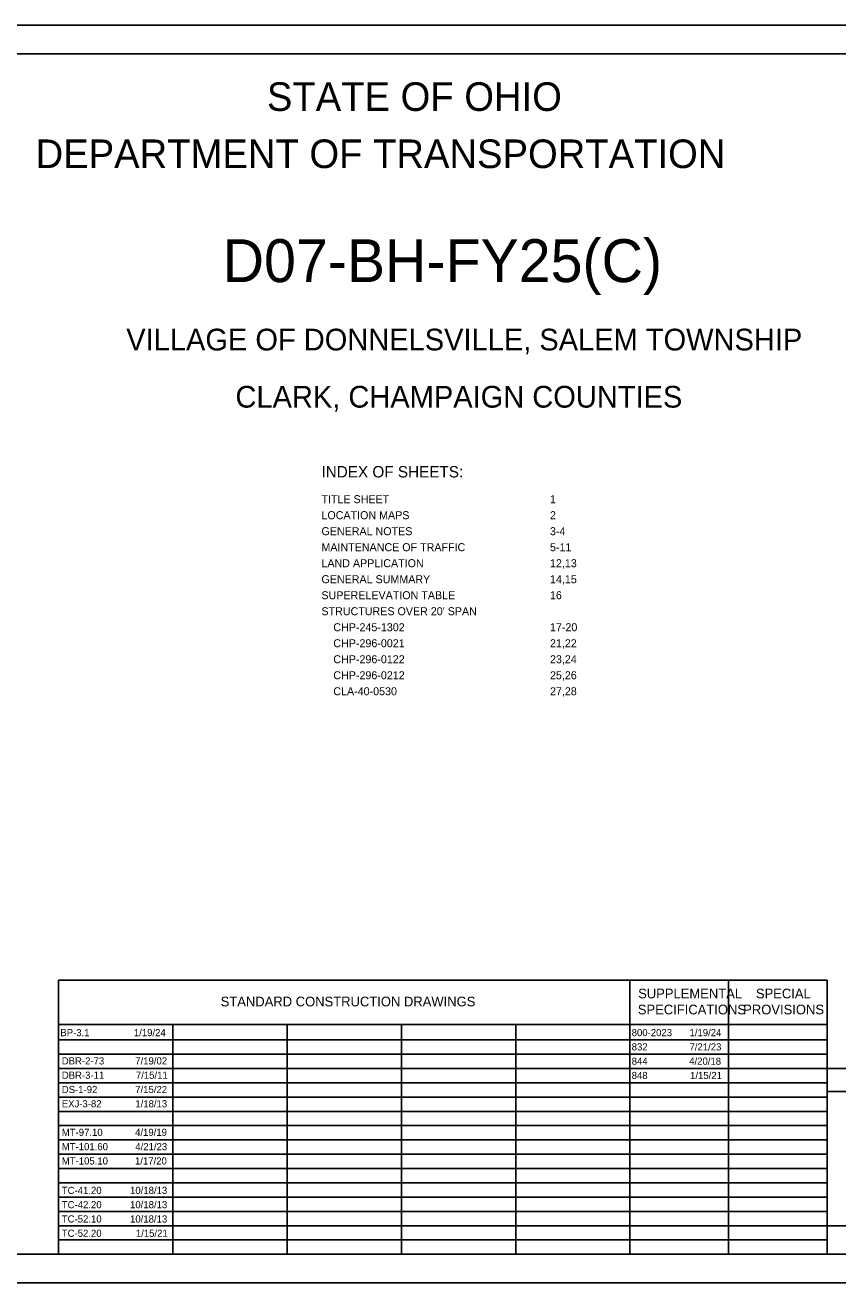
# Model space of a CAD drawing. Extents: x 0 to 36, y 0 to 22.
# Drawn here: x 9.56 to 23.79, y 0 to 22 of the extents above; entities that cross this region are included whole.
import ezdxf

# ---------------------------------------------------------------- set-up
doc = ezdxf.new("R2010")
doc.units = 0
for name, color, linetype in [('SH_Border', 7, 'Continuous'), ('SH_Cut_Line', 7, 'Continuous'), ('SH_Data', 7, 'Continuous'), ('SH_Text', 7, 'Continuous')]:
    doc.layers.add(name, color=color, linetype=linetype)

msp = doc.modelspace()

# ---------------------------------------------------------------- linework, layer by layer
at = {"layer": 'SH_Border'}
msp.add_lwpolyline([(1.5, 21.5), (33.5, 21.5), (33.5, 0.5), (1.5, 0.5)], close=True, dxfattribs=at)
at = {"layer": 'SH_Cut_Line'}
msp.add_lwpolyline([(0, 0), (34, 0), (34, 22), (0, 22)], close=True, dxfattribs=at)
at = {"layer": 'SH_Data'}
for p, q in [((10.15, 5.292), (23.6, 5.292)), ((10.15, 0.5), (10.15, 5.292)), ((20.15, 0.5), (20.15, 5.292)), ((21.875, 0.5), (21.875, 5.292)), ((23.6, 0.5), (23.6, 5.292)), ((10.15, 4.521), (23.6, 4.521)), ((12.15, 0.5), (12.15, 4.521)), ((14.15, 0.5), (14.15, 4.521)), ((16.15, 0.5), (16.15, 4.521)), ((18.15, 0.5), (18.15, 4.521)), ((10.15, 4.25), (23.6, 4.25)), ((10.15, 4), (23.6, 4)), ((10.15, 3.75), (23.6, 3.75)), ((23.6, 0.5), (23.6, 3.75)), ((23.6, 3.75), (26.4, 3.75)), ((10.15, 3.5), (23.6, 3.5)), ((23.6, 3.35), (26.4, 3.35)), ((10.15, 3.25), (23.6, 3.25)), ((10.15, 3), (23.6, 3)), ((10.15, 2.75), (23.6, 2.75)), ((10.15, 2.5), (23.6, 2.5)), ((10.15, 2.25), (23.6, 2.25)), ((10.15, 2), (23.6, 2)), ((10.15, 1.75), (23.6, 1.75)), ((10.15, 1.5), (23.6, 1.5)), ((10.15, 1.25), (23.6, 1.25)), ((10.15, 1), (23.6, 1)), ((10.15, 0.75), (23.6, 0.75)), ((23.6, 0.5), (26.4, 0.5))]:
    msp.add_line(p, q, dxfattribs=at)
msp.add_lwpolyline([(23.6, 0.5), (23.6, 1), (26.4, 1), (26.4, 0.5)], close=True, dxfattribs=at)

# ---------------------------------------------------------------- texts
at = {"layer": 'SH_Text'}
for s, height, p in [('STATE OF OHIO', 0.5, (13.795, 20.5)), ('DEPARTMENT OF TRANSPORTATION', 0.5, (9.747, 19.5)), ('D07-BH-FY25(C)', 0.75, (13.021, 17.505)), ('VILLAGE OF DONNELSVILLE, SALEM TOWNSHIP', 0.38, (11.334, 16.31)), ('CLARK, CHAMPAIGN COUNTIES', 0.38, (13.245, 15.31)), ('INDEX OF SHEETS:', 0.2, (14.75, 14.088)), ('TITLE SHEET ', 0.14, (14.75, 13.638)), ('1', 0.14, (18.75, 13.638)), ('LOCATION MAPS ', 0.14, (14.75, 13.358)), ('2', 0.14, (18.75, 13.358)), ('GENERAL NOTES     ', 0.14, (14.75, 13.078)), ('3-4', 0.14, (18.75, 13.078)), ('MAINTENANCE OF TRAFFIC    ', 0.14, (14.75, 12.798)), ('5-11', 0.14, (18.75, 12.798)), ('LAND APPLICATION     ', 0.14, (14.75, 12.518)), ('12,13', 0.14, (18.75, 12.518)), ('GENERAL SUMMARY ', 0.14, (14.75, 12.238)), ('14,15', 0.14, (18.75, 12.238)), ('SUPERELEVATION TABLE ', 0.14, (14.75, 11.958)), ('16', 0.14, (18.75, 11.958)), ("STRUCTURES OVER 20' SPAN ", 0.14, (14.75, 11.678)), ('    CHP-245-1302 ', 0.14, (14.75, 11.398)), ('17-20', 0.14, (18.75, 11.398)), ('    CHP-296-0021 ', 0.14, (14.75, 11.118)), ('21,22', 0.14, (18.75, 11.118)), ('    CHP-296-0122 ', 0.14, (14.75, 10.838)), ('23,24', 0.14, (18.75, 10.838)), ('    CHP-296-0212 ', 0.14, (14.75, 10.558)), ('25,26', 0.14, (18.75, 10.558)), ('    CLA-40-0530 ', 0.14, (14.75, 10.278)), ('27,28', 0.14, (18.75, 10.278)), ('SUPPLEMENTAL', 0.17, (20.293, 4.976)), ('SPECIAL', 0.17, (22.354, 4.976)), ('STANDARD CONSTRUCTION DRAWINGS', 0.17, (12.986, 4.836)), ('SPECIFICATIONS', 0.17, (20.287, 4.696)), ('PROVISIONS', 0.17, (22.132, 4.696)), ('BP-3.1', 0.125, (10.18, 4.315)), ('1/19/24', 0.125, (11.467, 4.315)), ('800-2023', 0.125, (20.18, 4.315)), ('1/19/24', 0.125, (21.192, 4.315)), ('832', 0.125, (20.18, 4.065)), ('7/21/23', 0.125, (21.192, 4.065)), ('DBR-2-73', 0.125, (10.205, 3.82)), ('7/19/02', 0.125, (11.491, 3.82)), ('844', 0.125, (20.18, 3.815)), ('4/20/18', 0.125, (21.187, 3.815)), ('DBR-3-11', 0.125, (10.205, 3.57)), ('7/15/11', 0.125, (11.502, 3.57)), ('848', 0.125, (20.18, 3.565)), ('1/15/21', 0.125, (21.202, 3.565)), ('DS-1-92', 0.125, (10.205, 3.32)), ('7/15/22', 0.125, (11.491, 3.32)), ('EXJ-3-82', 0.125, (10.205, 3.07)), ('1/18/13', 0.125, (11.492, 3.07)), ('MT-97.10', 0.125, (10.205, 2.57)), ('4/19/19', 0.125, (11.488, 2.57)), ('MT-101.60', 0.125, (10.205, 2.32)), ('4/21/23', 0.125, (11.492, 2.32)), ('1/17/20', 0.125, (11.486, 2.07)), ('MT-105.10', 0.125, (10.205, 2.07)), ('TC-41.20', 0.125, (10.205, 1.555)), ('10/18/13', 0.125, (11.4, 1.555)), ('TC-42.20', 0.125, (10.205, 1.305)), ('10/18/13', 0.125, (11.4, 1.305)), ('TC-52.10', 0.125, (10.205, 1.055)), ('10/18/13', 0.125, (11.4, 1.055)), ('TC-52.20', 0.125, (10.205, 0.805)), ('1/15/21', 0.125, (11.502, 0.805))]:
    msp.add_text(s, height=height, dxfattribs=at).set_placement(p)

doc.saveas('drawing.dxf')
